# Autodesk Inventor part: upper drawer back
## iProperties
Created: 2005-05
Part Number: upper drawer back
Material: mdf
Document SubType Name: Modeling
Designer: a.campbell
Manufacturer: Standard
Standards Organization: Custom
Author: a.campbell
Comments: machine to detail
length: 278
thickness: 12
width: 87
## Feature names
1. Extrusion1
